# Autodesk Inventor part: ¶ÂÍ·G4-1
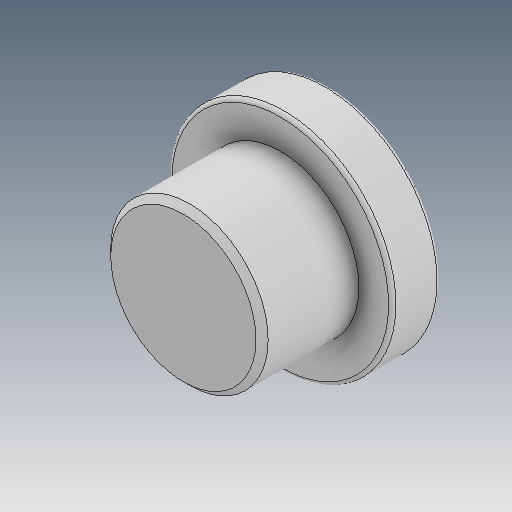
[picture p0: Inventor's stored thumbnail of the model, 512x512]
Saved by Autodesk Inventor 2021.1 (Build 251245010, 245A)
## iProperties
Created: 2018-07
Part Number: ¶ÂÍ·G4-1
Material: Ogólny
Document SubType Name: Modeling
Designer: user
Density: 1 g/cm^3
Appearance: Domyślna
Author: user
Revision Number: ÈÎºÎ
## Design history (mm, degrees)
feature "µ¹½Ç2"
node "Bryła1"
